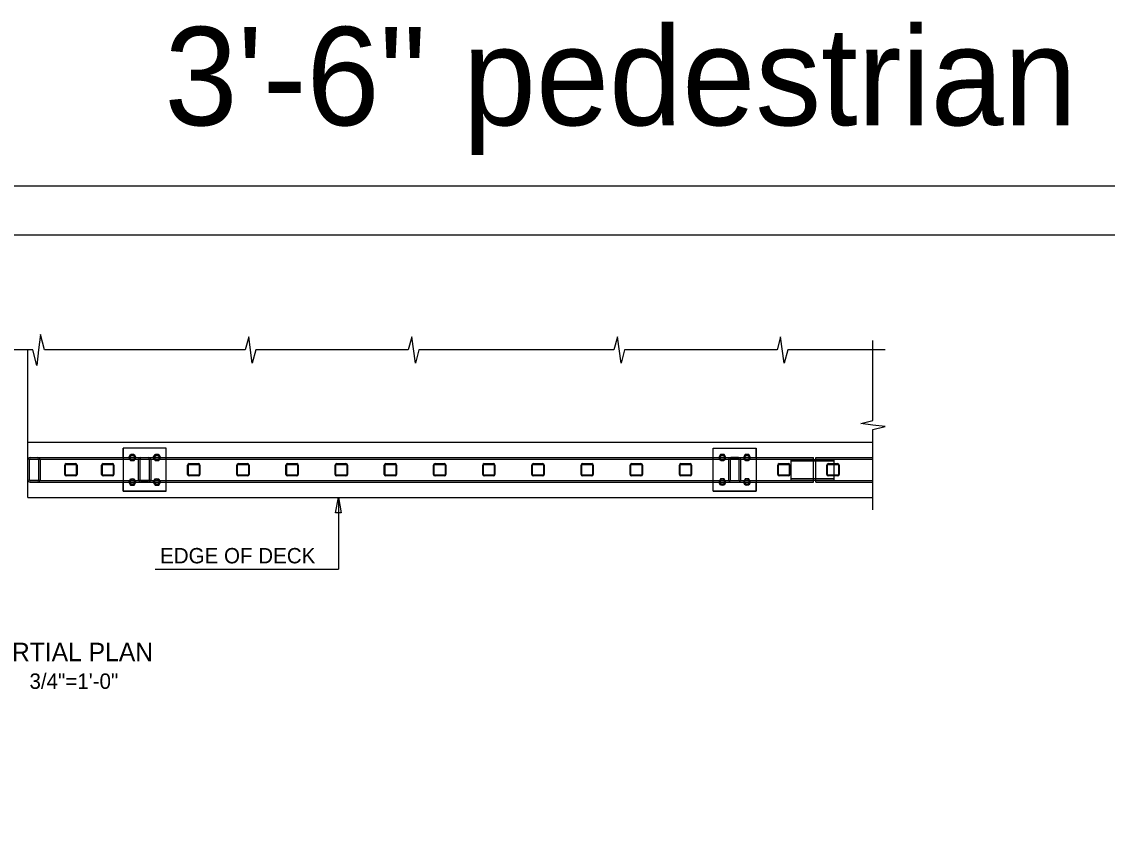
# Model space of a CAD drawing. Extents: x 0 to 22.7, y 0 to 15.8.
# Drawn here: x 7.61 to 14.97, y 10.3 to 15.78 of the extents above; entities that cross this region are included whole.
import ezdxf

# ---------------------------------------------------------------- set-up
doc = ezdxf.new("R2010")
doc.units = 0
for name, color, linetype in [('BORDER_ANNO_Cutsheet', 7, 'Continuous'), ('BRDG_ANNO_Anno-Sheet', 7, 'Continuous'), ('BRDG_ANNO_General-Notes', 7, 'Continuous'), ('BRDG_BASE_Hidden-Line', 7, 'Continuous'), ('BRDG_BASE_Obj-Line', 7, 'Continuous'), ('Default', 7, 'Continuous')]:
    doc.layers.add(name, color=color, linetype=linetype)

# ---------------------------------------------------------------- blocks, each defined once
blk = doc.blocks.new('TERM')
at = {"layer": 'Default'}
for p, q in [((-1.6, -0.27), (-1.6, 0.27)), ((-1.6, 0.27), (0, 0)), ((0, 0), (-1.6, -0.27))]:
    blk.add_line(p, q, dxfattribs=at)

msp = doc.modelspace()

# ---------------------------------------------------------------- linework, layer by layer
at = {"layer": 'BORDER_ANNO_Cutsheet'}
msp.add_lwpolyline([(0, 14.6667), (22.6667, 14.6667), (22.6667, 0), (0, 0)], close=True, dxfattribs=at)
at = {"layer": 'BRDG_ANNO_Anno-Sheet'}
msp.add_lwpolyline([(1, 14.3333), (22.3333, 14.3333), (22.3333, 0.3333), (1, 0.3333)], close=True, dxfattribs=at)
at = {"layer": 'BRDG_ANNO_General-Notes'}
for p in [(9.7592, 12.5529), (8.5177, 12.0665)]:
    msp.add_line(p, (9.7592, 12.0665), dxfattribs=at)
at = {"layer": 'BRDG_BASE_Hidden-Line'}
for p, q in [((7.6544, 12.6727), (7.6544, 12.8081)), ((7.6648, 12.6727), (7.6648, 12.8081)), ((7.67, 12.8238), (7.7221, 12.8238)), ((7.67, 12.8133), (7.7221, 12.8133)), ((7.7221, 12.8133), (12.9799, 12.8133)), ((7.7273, 12.8081), (7.7273, 12.6727)), ((7.7377, 12.8081), (7.7377, 12.6727)), ((8.4044, 12.6727), (8.4044, 12.8081)), ((8.4148, 12.6727), (8.4148, 12.8081)), ((8.42, 12.8238), (8.4721, 12.8238)), ((8.42, 12.8133), (8.4721, 12.8133)), ((8.4773, 12.8081), (8.4773, 12.6727)), ((8.4877, 12.8081), (8.4877, 12.6727)), ((12.4044, 12.8081), (12.4044, 12.6727)), ((12.4148, 12.8081), (12.4148, 12.6727)), ((12.4721, 12.8238), (12.42, 12.8238)), ((12.4721, 12.8133), (12.42, 12.8133)), ((12.4773, 12.6727), (12.4773, 12.8081)), ((12.4877, 12.6727), (12.4877, 12.8081)), ((12.8289, 12.6701), (12.8289, 12.8107)), ((12.8289, 12.8107), (13.1205, 12.8107)), ((12.9955, 12.8133), (13.3835, 12.8133)), ((13.1205, 12.6701), (13.1205, 12.8107)), ((12.8289, 12.8003), (13.1205, 12.8003)), ((7.7221, 12.6675), (7.67, 12.6675)), ((7.7221, 12.6675), (12.9799, 12.6675)), ((8.4721, 12.6675), (8.42, 12.6675)), ((12.42, 12.6675), (12.4721, 12.6675)), ((12.8289, 12.6805), (13.1205, 12.6805)), ((12.8289, 12.6701), (13.1205, 12.6701)), ((12.9955, 12.6675), (13.3835, 12.6675)), ((7.7221, 12.6571), (7.67, 12.6571)), ((8.4721, 12.6571), (8.42, 12.6571)), ((12.42, 12.6571), (12.4721, 12.6571))]:
    msp.add_line(p, q, dxfattribs=at)
for points in [[(8.5919, 12.8863), (8.3002, 12.8863), (8.3002, 12.5946), (8.5919, 12.5946)], [(12.3002, 12.8863), (12.5919, 12.8863), (12.5919, 12.5946), (12.3002, 12.5946)]]:
    msp.add_lwpolyline(points, close=True, dxfattribs=at)
for points in [[(8.3382, 12.8238), (8.3505, 12.8449), (8.3749, 12.8449), (8.3871, 12.8238)], [(8.3382, 12.8238), (8.3505, 12.8026), (8.3749, 12.8026), (8.3871, 12.8238)], [(8.5049, 12.8238), (8.5171, 12.8449), (8.5416, 12.8449), (8.5537, 12.8238)], [(8.5049, 12.8238), (8.5171, 12.8026), (8.5416, 12.8026), (8.5537, 12.8238)], [(12.3871, 12.8238), (12.3749, 12.8449), (12.3505, 12.8449), (12.3382, 12.8238)], [(12.3871, 12.8238), (12.3749, 12.8026), (12.3505, 12.8026), (12.3382, 12.8238)], [(12.5537, 12.8238), (12.5416, 12.8449), (12.5171, 12.8449), (12.5049, 12.8238)], [(12.5537, 12.8238), (12.5416, 12.8026), (12.5171, 12.8026), (12.5049, 12.8238)], [(7.9044, 12.7092), (7.9044, 12.7717)], [(7.9096, 12.7092), (7.9096, 12.7717)], [(7.9148, 12.7821), (7.9773, 12.7821)], [(7.9148, 12.7769), (7.9773, 12.7769)], [(7.9825, 12.7717), (7.9825, 12.7092)], [(7.9877, 12.7717), (7.9877, 12.7092)], [(8.1544, 12.7092), (8.1544, 12.7717)], [(8.1596, 12.7092), (8.1596, 12.7717)], [(8.1648, 12.7821), (8.2273, 12.7821)], [(8.1648, 12.7769), (8.2273, 12.7769)], [(8.2325, 12.7717), (8.2325, 12.7092)], [(8.2377, 12.7717), (8.2377, 12.7092)], [(8.7377, 12.7092), (8.7377, 12.7717)], [(8.7429, 12.7092), (8.7429, 12.7717)], [(8.7481, 12.7821), (8.8106, 12.7821)], [(8.7481, 12.7769), (8.8106, 12.7769)], [(8.8158, 12.7717), (8.8158, 12.7092)], [(8.821, 12.7717), (8.821, 12.7092)], [(9.071, 12.7092), (9.071, 12.7717)], [(9.0762, 12.7092), (9.0762, 12.7717)], [(9.0815, 12.7821), (9.144, 12.7821)], [(9.0815, 12.7769), (9.144, 12.7769)], [(9.1492, 12.7717), (9.1492, 12.7092)], [(9.1544, 12.7717), (9.1544, 12.7092)], [(9.4044, 12.7092), (9.4044, 12.7717)], [(9.4096, 12.7092), (9.4096, 12.7717)], [(9.4148, 12.7821), (9.4773, 12.7821)], [(9.4148, 12.7769), (9.4773, 12.7769)], [(9.4825, 12.7717), (9.4825, 12.7092)], [(9.4877, 12.7717), (9.4877, 12.7092)], [(9.7377, 12.7092), (9.7377, 12.7717)], [(9.7429, 12.7092), (9.7429, 12.7717)], [(9.7481, 12.7821), (9.8106, 12.7821)], [(9.7481, 12.7769), (9.8106, 12.7769)], [(9.8158, 12.7717), (9.8158, 12.7092)], [(9.821, 12.7717), (9.821, 12.7092)], [(10.071, 12.7092), (10.071, 12.7717)], [(10.0762, 12.7092), (10.0762, 12.7717)], [(10.0815, 12.7821), (10.144, 12.7821)], [(10.0815, 12.7769), (10.144, 12.7769)], [(10.1492, 12.7717), (10.1492, 12.7092)], [(10.1544, 12.7717), (10.1544, 12.7092)], [(10.4044, 12.7092), (10.4044, 12.7717)], [(10.4096, 12.7092), (10.4096, 12.7717)], [(10.4148, 12.7821), (10.4773, 12.7821)], [(10.4148, 12.7769), (10.4773, 12.7769)], [(10.4825, 12.7717), (10.4825, 12.7092)], [(10.4877, 12.7717), (10.4877, 12.7092)], [(10.7377, 12.7092), (10.7377, 12.7717)], [(10.7429, 12.7092), (10.7429, 12.7717)], [(10.7481, 12.7821), (10.8106, 12.7821)], [(10.7481, 12.7769), (10.8106, 12.7769)], [(10.8158, 12.7717), (10.8158, 12.7092)], [(10.821, 12.7717), (10.821, 12.7092)], [(11.071, 12.7092), (11.071, 12.7717)], [(11.0762, 12.7092), (11.0762, 12.7717)], [(11.0815, 12.7821), (11.144, 12.7821)], [(11.0815, 12.7769), (11.144, 12.7769)], [(11.1492, 12.7717), (11.1492, 12.7092)], [(11.1544, 12.7717), (11.1544, 12.7092)], [(11.4044, 12.7092), (11.4044, 12.7717)], [(11.4096, 12.7092), (11.4096, 12.7717)], [(11.4148, 12.7821), (11.4773, 12.7821)], [(11.4148, 12.7769), (11.4773, 12.7769)], [(11.4825, 12.7717), (11.4825, 12.7092)], [(11.4877, 12.7717), (11.4877, 12.7092)], [(11.7377, 12.7092), (11.7377, 12.7717)], [(11.7429, 12.7092), (11.7429, 12.7717)], [(11.7481, 12.7821), (11.8106, 12.7821)], [(11.7481, 12.7769), (11.8106, 12.7769)], [(11.8158, 12.7717), (11.8158, 12.7092)], [(11.821, 12.7717), (11.821, 12.7092)], [(12.071, 12.7092), (12.071, 12.7717)], [(12.0762, 12.7092), (12.0762, 12.7717)], [(12.0815, 12.7821), (12.144, 12.7821)], [(12.0815, 12.7769), (12.144, 12.7769)], [(12.1492, 12.7717), (12.1492, 12.7092)], [(12.1544, 12.7717), (12.1544, 12.7092)], [(12.7377, 12.7092), (12.7377, 12.7717)], [(12.7429, 12.7092), (12.7429, 12.7717)], [(12.7481, 12.7821), (12.8106, 12.7821)], [(12.7481, 12.7769), (12.8106, 12.7769)], [(12.8158, 12.7717), (12.8158, 12.7092)], [(12.821, 12.7717), (12.821, 12.7092)], [(13.071, 12.7092), (13.071, 12.7717)], [(13.0762, 12.7092), (13.0762, 12.7717)], [(13.0815, 12.7821), (13.144, 12.7821)], [(13.0815, 12.7769), (13.144, 12.7769)], [(13.1492, 12.7717), (13.1492, 12.7092)], [(13.1544, 12.7717), (13.1544, 12.7092)], [(7.9773, 12.704), (7.9148, 12.704)], [(7.9773, 12.6988), (7.9148, 12.6988)], [(8.2273, 12.704), (8.1648, 12.704)], [(8.2273, 12.6988), (8.1648, 12.6988)], [(8.3382, 12.6571), (8.3505, 12.6782), (8.3749, 12.6782), (8.3871, 12.6571)], [(8.5049, 12.6571), (8.5171, 12.6782), (8.5416, 12.6782), (8.5537, 12.6571)], [(8.8106, 12.704), (8.7481, 12.704)], [(8.8106, 12.6988), (8.7481, 12.6988)], [(9.144, 12.704), (9.0815, 12.704)], [(9.144, 12.6988), (9.0815, 12.6988)], [(9.4773, 12.704), (9.4148, 12.704)], [(9.4773, 12.6988), (9.4148, 12.6988)], [(9.8106, 12.704), (9.7481, 12.704)], [(9.8106, 12.6988), (9.7481, 12.6988)], [(10.144, 12.704), (10.0815, 12.704)], [(10.144, 12.6988), (10.0815, 12.6988)], [(10.4773, 12.704), (10.4148, 12.704)], [(10.4773, 12.6988), (10.4148, 12.6988)], [(10.8106, 12.704), (10.7481, 12.704)], [(10.8106, 12.6988), (10.7481, 12.6988)], [(11.144, 12.704), (11.0815, 12.704)], [(11.144, 12.6988), (11.0815, 12.6988)], [(11.4773, 12.704), (11.4148, 12.704)], [(11.4773, 12.6988), (11.4148, 12.6988)], [(11.8106, 12.704), (11.7481, 12.704)], [(11.8106, 12.6988), (11.7481, 12.6988)], [(12.144, 12.704), (12.0815, 12.704)], [(12.144, 12.6988), (12.0815, 12.6988)], [(12.3871, 12.6571), (12.3749, 12.6782), (12.3505, 12.6782), (12.3382, 12.6571)], [(12.5537, 12.6571), (12.5416, 12.6782), (12.5171, 12.6782), (12.5049, 12.6571)], [(12.8106, 12.704), (12.7481, 12.704)], [(12.8106, 12.6988), (12.7481, 12.6988)], [(13.144, 12.704), (13.0815, 12.704)], [(13.144, 12.6988), (13.0815, 12.6988)]]:
    msp.add_lwpolyline(points, dxfattribs=at)
for centre in [(8.3627, 12.8238), (8.5293, 12.8238), (12.3627, 12.8238), (12.5293, 12.8238), (8.3627, 12.6571), (8.5293, 12.6571), (12.3627, 12.6571), (12.5293, 12.6571)]:
    msp.add_circle(centre, 0.0143, dxfattribs=at)
for centre, radius, start, end in [((7.67, 12.8081), 0.0156, 90, 180), ((7.67, 12.8081), 0.00521, 90, 180), ((7.7221, 12.8081), 0.0156, 0, 90), ((7.7221, 12.8081), 0.00521, 0, 90), ((8.3627, 12.8238), 0.0212, 0, 180), ((8.3627, 12.8238), 0.0212, 180, 0), ((8.42, 12.8081), 0.0156, 90, 180), ((8.42, 12.8081), 0.00521, 90, 180), ((8.4721, 12.8081), 0.0156, 0, 90), ((8.4721, 12.8081), 0.00521, 0, 90), ((8.5293, 12.8238), 0.0212, 0, 180), ((8.5293, 12.8238), 0.0212, 180, 0), ((12.3627, 12.8238), 0.0212, 0, 180), ((12.3627, 12.8238), 0.0212, 180, 0), ((12.4199, 12.8081), 0.0156, 90, 180), ((12.4199, 12.8081), 0.00521, 90, 180), ((12.472, 12.8081), 0.0156, 0, 90), ((12.472, 12.8081), 0.00521, 0, 90), ((12.5293, 12.8238), 0.0212, 0, 180), ((12.5293, 12.8238), 0.0212, 180, 0), ((7.9148, 12.7717), 0.0104, 90, 180), ((7.9148, 12.7717), 0.00521, 90, 180), ((7.9773, 12.7717), 0.0104, 0, 90), ((7.9773, 12.7717), 0.00521, 0, 90), ((8.1648, 12.7717), 0.0104, 90, 180), ((8.1648, 12.7717), 0.00521, 90, 180), ((8.2273, 12.7717), 0.0104, 0, 90), ((8.2273, 12.7717), 0.00521, 0, 90), ((8.7481, 12.7717), 0.0104, 90, 180), ((8.7481, 12.7717), 0.00521, 90, 180), ((8.8106, 12.7717), 0.0104, 0, 90), ((8.8106, 12.7717), 0.00521, 0, 90), ((9.0814, 12.7717), 0.0104, 90, 180), ((9.0814, 12.7717), 0.00521, 90, 180), ((9.1439, 12.7717), 0.0104, 0, 90), ((9.1439, 12.7717), 0.00521, 0, 90), ((9.4148, 12.7717), 0.0104, 90, 180), ((9.4148, 12.7717), 0.00521, 90, 180), ((9.4773, 12.7717), 0.0104, 0, 90), ((9.4773, 12.7717), 0.00521, 0, 90), ((9.7481, 12.7717), 0.0104, 90, 180), ((9.7481, 12.7717), 0.00521, 90, 180), ((9.8106, 12.7717), 0.0104, 0, 90), ((9.8106, 12.7717), 0.00521, 0, 90), ((10.0814, 12.7717), 0.0104, 90, 180), ((10.0814, 12.7717), 0.00521, 90, 180), ((10.1439, 12.7717), 0.0104, 0, 90), ((10.1439, 12.7717), 0.00521, 0, 90), ((10.4148, 12.7717), 0.0104, 90, 180), ((10.4148, 12.7717), 0.00521, 90, 180), ((10.4773, 12.7717), 0.0104, 0, 90), ((10.4773, 12.7717), 0.00521, 0, 90), ((10.7481, 12.7717), 0.0104, 90, 180), ((10.7481, 12.7717), 0.00521, 90, 180), ((10.8106, 12.7717), 0.0104, 0, 90), ((10.8106, 12.7717), 0.00521, 0, 90), ((11.0814, 12.7717), 0.0104, 90, 180), ((11.0814, 12.7717), 0.00521, 90, 180), ((11.1439, 12.7717), 0.0104, 0, 90), ((11.1439, 12.7717), 0.00521, 0, 90), ((11.4148, 12.7717), 0.0104, 90, 180), ((11.4148, 12.7717), 0.00521, 90, 180), ((11.4773, 12.7717), 0.0104, 0, 90), ((11.4773, 12.7717), 0.00521, 0, 90), ((11.7481, 12.7717), 0.0104, 90, 180), ((11.7481, 12.7717), 0.00521, 90, 180), ((11.8106, 12.7717), 0.0104, 0, 90), ((11.8106, 12.7717), 0.00521, 0, 90), ((12.0814, 12.7717), 0.0104, 90, 180), ((12.0814, 12.7717), 0.00521, 90, 180), ((12.1439, 12.7717), 0.0104, 0, 90), ((12.1439, 12.7717), 0.00521, 0, 90), ((12.7481, 12.7717), 0.0104, 90, 180), ((12.7481, 12.7717), 0.00521, 90, 180), ((12.8106, 12.7717), 0.0104, 0, 90), ((12.8106, 12.7717), 0.00521, 0, 90), ((13.0814, 12.7717), 0.0104, 90, 180), ((13.0814, 12.7717), 0.00521, 90, 180), ((13.1439, 12.7717), 0.0104, 0, 90), ((13.1439, 12.7717), 0.00521, 0, 90), ((7.67, 12.6727), 0.0156, 180, 270), ((7.67, 12.6727), 0.00521, 180, 270), ((7.7221, 12.6727), 0.00521, 270, 0), ((7.7221, 12.6727), 0.0156, 270, 0), ((7.9148, 12.7092), 0.0104, 180, 270), ((7.9148, 12.7092), 0.00521, 180, 270), ((7.9773, 12.7092), 0.0104, 270, 360), ((7.9773, 12.7092), 0.00521, 270, 360), ((8.1648, 12.7092), 0.0104, 180, 270), ((8.1648, 12.7092), 0.00521, 180, 270), ((8.2273, 12.7092), 0.0104, 270, 360), ((8.2273, 12.7092), 0.00521, 270, 360), ((8.3627, 12.6571), 0.0212, 0, 180), ((8.42, 12.6727), 0.0156, 180, 270), ((8.42, 12.6727), 0.00521, 180, 270), ((8.4721, 12.6727), 0.00521, 270, 0), ((8.4721, 12.6727), 0.0156, 270, 0), ((8.5293, 12.6571), 0.0212, 0, 180), ((8.7481, 12.7092), 0.0104, 180, 270), ((8.7481, 12.7092), 0.00521, 180, 270), ((8.8106, 12.7092), 0.0104, 270, 360), ((8.8106, 12.7092), 0.00521, 270, 360), ((9.0814, 12.7092), 0.0104, 180, 270), ((9.0814, 12.7092), 0.00521, 180, 270), ((9.1439, 12.7092), 0.0104, 270, 360), ((9.1439, 12.7092), 0.00521, 270, 360), ((9.4148, 12.7092), 0.0104, 180, 270), ((9.4148, 12.7092), 0.00521, 180, 270), ((9.4773, 12.7092), 0.0104, 270, 360), ((9.4773, 12.7092), 0.00521, 270, 360), ((9.7481, 12.7092), 0.0104, 180, 270), ((9.7481, 12.7092), 0.00521, 180, 270), ((9.8106, 12.7092), 0.0104, 270, 360), ((9.8106, 12.7092), 0.00521, 270, 360), ((10.0814, 12.7092), 0.0104, 180, 270), ((10.0814, 12.7092), 0.00521, 180, 270), ((10.1439, 12.7092), 0.0104, 270, 360), ((10.1439, 12.7092), 0.00521, 270, 360), ((10.4148, 12.7092), 0.0104, 180, 270), ((10.4148, 12.7092), 0.00521, 180, 270), ((10.4773, 12.7092), 0.0104, 270, 360), ((10.4773, 12.7092), 0.00521, 270, 360), ((10.7481, 12.7092), 0.0104, 180, 270), ((10.7481, 12.7092), 0.00521, 180, 270), ((10.8106, 12.7092), 0.0104, 270, 360), ((10.8106, 12.7092), 0.00521, 270, 360), ((11.0814, 12.7092), 0.0104, 180, 270), ((11.0814, 12.7092), 0.00521, 180, 270), ((11.1439, 12.7092), 0.0104, 270, 360), ((11.1439, 12.7092), 0.00521, 270, 360), ((11.4148, 12.7092), 0.0104, 180, 270), ((11.4148, 12.7092), 0.00521, 180, 270), ((11.4773, 12.7092), 0.0104, 270, 360), ((11.4773, 12.7092), 0.00521, 270, 360), ((11.7481, 12.7092), 0.0104, 180, 270), ((11.7481, 12.7092), 0.00521, 180, 270), ((11.8106, 12.7092), 0.0104, 270, 360), ((11.8106, 12.7092), 0.00521, 270, 360), ((12.0814, 12.7092), 0.0104, 180, 270), ((12.0814, 12.7092), 0.00521, 180, 270), ((12.1439, 12.7092), 0.0104, 270, 360), ((12.1439, 12.7092), 0.00521, 270, 360), ((12.3627, 12.6571), 0.0212, 0, 180), ((12.4199, 12.6727), 0.0156, 180, 270), ((12.4199, 12.6727), 0.00521, 180, 270), ((12.472, 12.6727), 0.00521, 270, 0), ((12.472, 12.6727), 0.0156, 270, 0), ((12.5293, 12.6571), 0.0212, 0, 180), ((12.7481, 12.7092), 0.0104, 180, 270), ((12.7481, 12.7092), 0.00521, 180, 270), ((12.8106, 12.7092), 0.0104, 270, 360), ((12.8106, 12.7092), 0.00521, 270, 360), ((13.0814, 12.7092), 0.0104, 180, 270), ((13.0814, 12.7092), 0.00521, 180, 270), ((13.1439, 12.7092), 0.0104, 270, 360), ((13.1439, 12.7092), 0.00521, 270, 360)]:
    msp.add_arc(centre, radius, start, end, dxfattribs=at)
at = {"layer": 'BRDG_BASE_Obj-Line'}
for p, q in [((7.6544, 12.5529), (7.6544, 13.5529)), ((7.6544, 12.9279), (13.3835, 12.9279)), ((8.5919, 12.8863), (8.3002, 12.8863)), ((8.3002, 12.8238), (8.3002, 12.8863)), ((8.5919, 12.8238), (8.5919, 12.8863)), ((12.3002, 12.8863), (12.5919, 12.8863)), ((12.3002, 12.8238), (12.3002, 12.8863)), ((12.5919, 12.8238), (12.5919, 12.8863)), ((7.6544, 12.6727), (7.6544, 12.8081)), ((7.6648, 12.8238), (12.9799, 12.8238)), ((12.9799, 12.6571), (12.9799, 12.8238)), ((12.9799, 12.8107), (12.9955, 12.8107)), ((12.9955, 12.6571), (12.9955, 12.8238)), ((12.9955, 12.8238), (13.3835, 12.8238)), ((12.9799, 12.6701), (12.9955, 12.6701)), ((7.67, 12.6571), (12.9799, 12.6571)), ((8.3002, 12.5946), (8.3002, 12.6571)), ((8.5919, 12.5946), (8.3002, 12.5946)), ((8.5919, 12.5946), (8.5919, 12.6571)), ((12.3002, 12.5946), (12.3002, 12.6571)), ((12.3002, 12.5946), (12.5919, 12.5946)), ((12.5919, 12.5946), (12.5919, 12.6571)), ((12.9955, 12.6571), (13.3835, 12.6571)), ((7.6544, 12.5529), (13.3835, 12.5529))]:
    msp.add_line(p, q, dxfattribs=at)
for points in [[(8.4669, 13.5529), (7.7669, 13.5529), (7.7405, 13.6586), (7.7273, 13.5529), (7.7141, 13.4472), (7.6876, 13.5529), (6.9877, 13.5529)], [(10.9669, 13.5529), (10.3058, 13.5529), (10.2818, 13.4627), (10.2577, 13.6432), (10.2337, 13.5529), (9.7169, 13.5529), (9.2, 13.5529), (9.176, 13.4627), (9.152, 13.6432), (9.1279, 13.5529), (8.4669, 13.5529)], [(13.4669, 13.5529), (12.8058, 13.5529), (12.7818, 13.4627), (12.7577, 13.6432), (12.7337, 13.5529), (12.2169, 13.5529), (11.7, 13.5529), (11.676, 13.4627), (11.652, 13.6432), (11.6279, 13.5529), (10.9669, 13.5529)], [(13.3835, 12.4696), (13.3835, 13.0128), (13.4655, 13.0333), (13.3835, 13.0436), (13.3015, 13.0539), (13.3835, 13.0744), (13.3835, 13.6176)], [(8.3382, 12.8238), (8.3505, 12.8449), (8.3749, 12.8449), (8.3871, 12.8238)], [(8.5049, 12.8238), (8.5171, 12.8449), (8.5416, 12.8449), (8.5537, 12.8238)], [(12.3871, 12.8238), (12.3749, 12.8449), (12.3505, 12.8449), (12.3382, 12.8238)], [(12.5537, 12.8238), (12.5416, 12.8449), (12.5171, 12.8449), (12.5049, 12.8238)], [(8.3382, 12.6571), (8.3505, 12.6359), (8.3749, 12.6359), (8.3871, 12.6571)], [(8.5049, 12.6571), (8.5171, 12.6359), (8.5416, 12.6359), (8.5537, 12.6571)], [(12.3871, 12.6571), (12.3749, 12.6359), (12.3505, 12.6359), (12.3382, 12.6571)], [(12.5537, 12.6571), (12.5416, 12.6359), (12.5171, 12.6359), (12.5049, 12.6571)]]:
    msp.add_lwpolyline(points, dxfattribs=at)
for centre, radius, start, end in [((7.67, 12.8081), 0.0156, 90, 180), ((8.3627, 12.8238), 0.0212, 0, 180), ((8.5293, 12.8238), 0.0212, 0, 180), ((12.3627, 12.8238), 0.0212, 0, 180), ((12.5293, 12.8238), 0.0212, 0, 180), ((7.67, 12.6727), 0.0156, 180, 270), ((8.3627, 12.6571), 0.0212, 180, 0), ((8.5293, 12.6571), 0.0212, 180, 0), ((12.3627, 12.6571), 0.0212, 180, 0), ((12.5293, 12.6571), 0.0212, 180, 0)]:
    msp.add_arc(centre, radius, start, end, dxfattribs=at)

# ---------------------------------------------------------------- block references
at = {"layer": 'BRDG_ANNO_General-Notes', "xscale": 0.06510416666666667, "yscale": 0.0732421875, "rotation": 90}
msp.add_blockref('TERM', (9.7592, 12.5529), dxfattribs=at)

# ---------------------------------------------------------------- texts
at = {"layer": 'BRDG_ANNO_Anno-Sheet'}
msp.add_text('3\'-6" pedestrian', height=0.666667, dxfattribs=at).set_placement((8.5803, 15.0766))
at = {"layer": 'BRDG_ANNO_General-Notes'}
for s, height, p in [('EDGE OF DECK', 0.104167, (8.5507, 12.1061)), ('PARTIAL PLAN', 0.125, (7.3235, 11.4428)), ('3/4"=1\'-0"', 0.10417, (7.6653, 11.2553))]:
    msp.add_text(s, height=height, dxfattribs=at).set_placement(p)

doc.saveas('drawing.dxf')
